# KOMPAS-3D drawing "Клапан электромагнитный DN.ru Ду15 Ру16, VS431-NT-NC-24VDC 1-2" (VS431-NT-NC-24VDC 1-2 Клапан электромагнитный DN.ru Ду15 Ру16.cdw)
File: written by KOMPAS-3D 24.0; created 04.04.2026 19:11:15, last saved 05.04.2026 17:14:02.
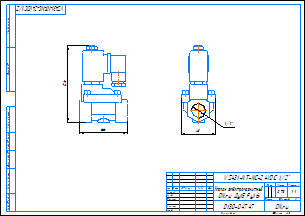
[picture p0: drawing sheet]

Document properties: c3d_UniqueCompID: ef56311e-7521-43dc-8291-0e6108b3d81d; Обозначение: VS400-ET-NC-220VAC 1-2; Наименование: Клапан электромагнитный DN.ru Ду15 Ру16; Автор: artio; Класс точности: c; Знак неуказанной шероховатости: Шероховатость не задана; Рассекать на разрезах: Да; c3d_UniqueCompID: ef56311e-7521-43dc-8291-0e6108b3d81d; Обозначение: VS400-ET-NC-220VAC 3-8; Наименование: Клапан электромагнитный DN.ru Ду10 Ру16; Автор: artio; Класс точности: c; Знак неуказанной шероховатости: Шероховатость не задана; Рассекать на разрезах: Да; Автор: artio; Форматы листов документа: A3; Полное имя файла: VS431-NT-NC-24VDC 1-2 Клапан электромагнитный DN.ru Ду15 Ру16.m3d; Масса: 0.732; Наименование: Клапан электромагнитный DN.ru Ду15 Ру16; Количество листов документа: 1; Примечание: D130-04747

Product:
- Body: Тело 1  | qty 1
    Масса: 1.030062
- Part/product: Клапан электромагнитный DN.ru Ду15 Ру16  | designation VS431-NT-NC-24VDC 1-2
    Масса: 0.732
    Раздел спецификации: Прочие изделия
    Примечание: D130-04747
    additional columns: ef56311e-7521-43dc-8291-0e6108b3d81d; VS400-ET-NC-220VAC 1-2; artio; c; Шероховатость не задана; Да

Views: Вид 1, Спереди, Проекционный вид 2
Referenced files in C:\Users\artio\OneDrive\Рабочий стол\Клапан электромагнитный DN.ru\VS400-ET-NC\VS400-ET-NC-24VDC\: VS400-ET-NC-24VDC 3-8 Клапан электромагнитный DN.ru Ду10 Ру16.m3d
Referenced files in C:\Users\artio\OneDrive\Рабочий стол\Клапан электромагнитный DN.ru\VS431\VS431-NT-NC\VS431-NT-NC-24VDC\Ду15\: VS431-NT-NC-24VDC 1-2 Клапан электромагнитный DN.ru Ду15 Ру16.m3d
Referenced files in C:\Users\artio\OneDrive\Рабочий стол\Клапан электромагнитный DN.ru\VS400-ET-NC\: VS400-ET-NC-24VDC 3-8 Клапан электромагнитный DN.ru Ду10 Ру16.cdw
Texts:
  VS431-NT-NC-24VDC 1-2
  Клапан электромагнитный
  DN.ru Ду15 Ру16
  VS431-NT-NC-24VDC 1/2"
  VS431-NT-NC-24VDC 1/2"-
  Клапан электромагнитный DN.ru Ду15 Ру16
  VS431-NT-NC-24VDC 1-2 Клапан электромагнитный DN.ru Ду15 Ру16
Dimensions and other numbers on the sheet: 0; 3; 2; 4; 48; 1/2"; 66; 106; 1:1; 1; 0,73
